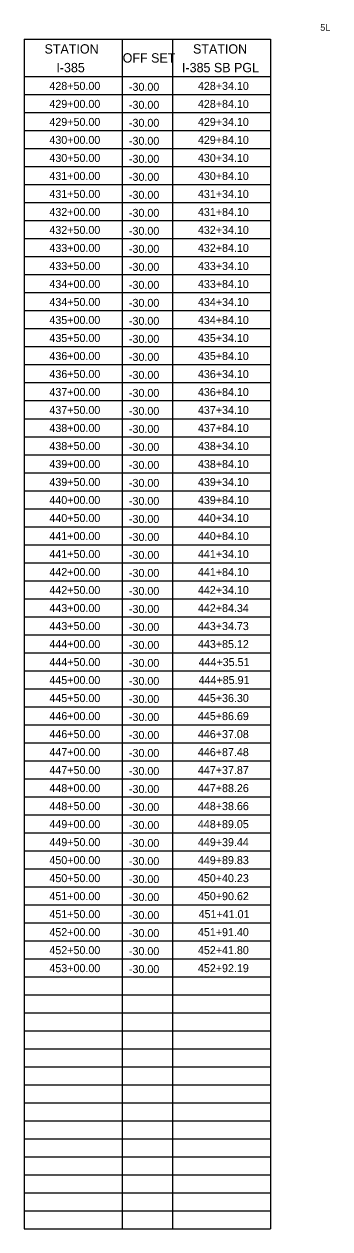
# Model space of a CAD drawing. Extents: x 1602163 to 1612907, y 1087635 to 1096265.
# Drawn here: x 1610961 to 1611190, y 1095298 to 1096201 of the extents above; entities that cross this region are included whole.
import ezdxf

# ---------------------------------------------------------------- set-up
doc = ezdxf.new("R2010")
doc.units = 0
for name, color, linetype in [('RD_SHT_Bndy', 7, 'Continuous'), ('RD_SHT_Misc1', 7, 'Continuous'), ('RD_SHT_TX', 7, 'Continuous')]:
    doc.layers.add(name, color=color, linetype=linetype)

msp = doc.modelspace()

# ---------------------------------------------------------------- linework, layer by layer
at = {"layer": 'RD_SHT_Misc1'}
for p, q in [((1610961.15, 1096189.84), (1610961.15, 1095297.84)), ((1610961.15, 1096189.84), (1611145.98, 1096189.84)), ((1611034.62, 1096189.84), (1611034.62, 1095297.84)), ((1611072.51, 1096189.84), (1611072.51, 1095297.84)), ((1611145.98, 1096189.84), (1611145.98, 1095297.84)), ((1610961.15, 1096161.84), (1611145.98, 1096161.84)), ((1610961.15, 1096148.34), (1611145.98, 1096148.34)), ((1610961.15, 1096134.84), (1611145.98, 1096134.84)), ((1610961.15, 1096121.34), (1611145.98, 1096121.34)), ((1610961.15, 1096107.84), (1611145.98, 1096107.84)), ((1610961.15, 1096094.34), (1611145.98, 1096094.34)), ((1610961.15, 1096080.84), (1611145.98, 1096080.84)), ((1610961.15, 1096067.34), (1611145.98, 1096067.34)), ((1610961.15, 1096053.84), (1611145.98, 1096053.84)), ((1610961.15, 1096040.34), (1611145.98, 1096040.34)), ((1610961.15, 1096026.84), (1611145.98, 1096026.84)), ((1610961.15, 1096013.34), (1611145.98, 1096013.34)), ((1610961.15, 1095999.84), (1611145.98, 1095999.84)), ((1610961.15, 1095986.34), (1611145.98, 1095986.34)), ((1610961.15, 1095972.84), (1611145.98, 1095972.84)), ((1610961.15, 1095959.34), (1611145.98, 1095959.34)), ((1610961.15, 1095945.84), (1611145.98, 1095945.84)), ((1610961.15, 1095932.34), (1611145.98, 1095932.34)), ((1610961.15, 1095918.84), (1611145.98, 1095918.84)), ((1610961.15, 1095905.34), (1611145.98, 1095905.34)), ((1610961.15, 1095891.84), (1611145.98, 1095891.84)), ((1610961.15, 1095878.34), (1611145.98, 1095878.34)), ((1610961.15, 1095864.84), (1611145.98, 1095864.84)), ((1610961.15, 1095851.34), (1611145.98, 1095851.34)), ((1610961.15, 1095837.84), (1611145.98, 1095837.84)), ((1610961.15, 1095824.34), (1611145.98, 1095824.34)), ((1610961.15, 1095810.84), (1611145.98, 1095810.84)), ((1610961.15, 1095797.34), (1611145.98, 1095797.34)), ((1610961.15, 1095783.84), (1611145.98, 1095783.84)), ((1610961.15, 1095770.34), (1611145.98, 1095770.34)), ((1610961.15, 1095756.84), (1611145.98, 1095756.84)), ((1610961.15, 1095743.34), (1611145.98, 1095743.34)), ((1610961.15, 1095729.84), (1611145.98, 1095729.84)), ((1610961.15, 1095716.34), (1611145.98, 1095716.34)), ((1610961.15, 1095702.84), (1611145.98, 1095702.84)), ((1610961.15, 1095689.34), (1611145.98, 1095689.34)), ((1610961.15, 1095675.84), (1611145.98, 1095675.84)), ((1610961.15, 1095662.34), (1611145.98, 1095662.34)), ((1610961.15, 1095648.84), (1611145.98, 1095648.84)), ((1610961.15, 1095635.34), (1611145.98, 1095635.34)), ((1610961.15, 1095621.84), (1611145.98, 1095621.84)), ((1610961.15, 1095608.34), (1611145.98, 1095608.34)), ((1610961.15, 1095594.84), (1611145.98, 1095594.84)), ((1610961.15, 1095581.34), (1611145.98, 1095581.34)), ((1610961.15, 1095567.84), (1611145.98, 1095567.84)), ((1610961.15, 1095554.34), (1611145.98, 1095554.34)), ((1610961.15, 1095540.84), (1611145.98, 1095540.84)), ((1610961.15, 1095527.34), (1611145.98, 1095527.34)), ((1610961.15, 1095513.84), (1611145.98, 1095513.84)), ((1610961.15, 1095500.34), (1611145.98, 1095500.34)), ((1610961.15, 1095486.84), (1611145.98, 1095486.84)), ((1610961.15, 1095473.34), (1611145.98, 1095473.34)), ((1610961.15, 1095459.84), (1611145.98, 1095459.84)), ((1610961.15, 1095446.34), (1611145.98, 1095446.34)), ((1610961.15, 1095432.84), (1611145.98, 1095432.84)), ((1610961.15, 1095419.34), (1611145.98, 1095419.34)), ((1610961.15, 1095405.84), (1611145.98, 1095405.84)), ((1610961.15, 1095392.34), (1611145.98, 1095392.34)), ((1610961.15, 1095378.84), (1611145.98, 1095378.84)), ((1610961.15, 1095365.34), (1611145.98, 1095365.34)), ((1610961.15, 1095351.84), (1611145.98, 1095351.84)), ((1610961.15, 1095338.34), (1611145.98, 1095338.34)), ((1610961.15, 1095324.84), (1611145.98, 1095324.84)), ((1610961.15, 1095311.34), (1611145.98, 1095311.34)), ((1610961.15, 1095297.84), (1611145.98, 1095297.84))]:
    msp.add_line(p, q, dxfattribs=at)

# ---------------------------------------------------------------- texts
at = {"layer": 'RD_SHT_Bndy'}
msp.add_text('5L', height=5, dxfattribs=at).set_placement((1611183.24, 1096196.19))
at = {"layer": 'RD_SHT_TX'}
for s, height, p in [('STATION', 7, (1610976.47, 1096179.07)), ('OFF SET', 7, (1611035.07, 1096172.34)), ('STATION', 7, (1611087.83, 1096179.07)), ('I-385', 7, (1610985.34, 1096165.07)), ('I-385 SB PGL', 7, (1611079.55, 1096165.07)), ('428+50.00', 6, (1610980.14, 1096151.84)), ('-30.00', 6, (1611039.78, 1096151.15)), ('428+34.10', 6, (1611091.5, 1096151.84)), ('429+00.00', 6, (1610980.14, 1096138.34)), ('-30.00', 6, (1611039.78, 1096137.65)), ('428+84.10', 6, (1611091.5, 1096138.34)), ('429+50.00', 6, (1610980.14, 1096124.84)), ('-30.00', 6, (1611039.78, 1096124.15)), ('429+34.10', 6, (1611091.5, 1096124.84)), ('430+00.00', 6, (1610980.14, 1096111.34)), ('-30.00', 6, (1611039.78, 1096110.65)), ('429+84.10', 6, (1611091.5, 1096111.34)), ('430+50.00', 6, (1610980.14, 1096097.84)), ('-30.00', 6, (1611039.78, 1096097.15)), ('430+34.10', 6, (1611091.5, 1096097.84)), ('431+00.00', 6, (1610980.14, 1096084.34)), ('-30.00', 6, (1611039.78, 1096083.65)), ('430+84.10', 6, (1611091.5, 1096084.34)), ('431+50.00', 6, (1610980.14, 1096070.84)), ('-30.00', 6, (1611039.78, 1096070.15)), ('431+34.10', 6, (1611091.5, 1096070.84)), ('432+00.00', 6, (1610980.14, 1096057.34)), ('-30.00', 6, (1611039.78, 1096056.65)), ('431+84.10', 6, (1611091.5, 1096057.34)), ('432+50.00', 6, (1610980.14, 1096043.84)), ('-30.00', 6, (1611039.78, 1096043.15)), ('432+34.10', 6, (1611091.5, 1096043.84)), ('433+00.00', 6, (1610980.14, 1096030.34)), ('-30.00', 6, (1611039.78, 1096029.65)), ('432+84.10', 6, (1611091.5, 1096030.34)), ('433+50.00', 6, (1610980.14, 1096016.84)), ('-30.00', 6, (1611039.78, 1096016.15)), ('433+34.10', 6, (1611091.5, 1096016.84)), ('434+00.00', 6, (1610980.14, 1096003.34)), ('-30.00', 6, (1611039.78, 1096002.65)), ('433+84.10', 6, (1611091.5, 1096003.34)), ('434+50.00', 6, (1610980.14, 1095989.84)), ('-30.00', 6, (1611039.78, 1095989.15)), ('434+34.10', 6, (1611091.5, 1095989.84)), ('435+00.00', 6, (1610980.14, 1095976.34)), ('-30.00', 6, (1611039.78, 1095975.65)), ('434+84.10', 6, (1611091.5, 1095976.34)), ('435+50.00', 6, (1610980.14, 1095962.84)), ('-30.00', 6, (1611039.78, 1095962.15)), ('435+34.10', 6, (1611091.5, 1095962.84)), ('436+00.00', 6, (1610980.14, 1095949.34)), ('-30.00', 6, (1611039.78, 1095948.65)), ('435+84.10', 6, (1611091.5, 1095949.34)), ('436+50.00', 6, (1610980.14, 1095935.84)), ('-30.00', 6, (1611039.78, 1095935.15)), ('436+34.10', 6, (1611091.5, 1095935.84)), ('437+00.00', 6, (1610980.14, 1095922.34)), ('-30.00', 6, (1611039.78, 1095921.65)), ('436+84.10', 6, (1611091.5, 1095922.34)), ('437+50.00', 6, (1610980.14, 1095908.84)), ('-30.00', 6, (1611039.78, 1095908.15)), ('437+34.10', 6, (1611091.5, 1095908.84)), ('438+00.00', 6, (1610980.14, 1095895.34)), ('-30.00', 6, (1611039.78, 1095894.65)), ('437+84.10', 6, (1611091.5, 1095895.34)), ('438+50.00', 6, (1610980.14, 1095881.84)), ('-30.00', 6, (1611039.78, 1095881.15)), ('438+34.10', 6, (1611091.5, 1095881.84)), ('439+00.00', 6, (1610980.14, 1095868.34)), ('-30.00', 6, (1611039.78, 1095867.65)), ('438+84.10', 6, (1611091.5, 1095868.34)), ('439+50.00', 6, (1610980.14, 1095854.84)), ('-30.00', 6, (1611039.78, 1095854.15)), ('439+34.10', 6, (1611091.5, 1095854.84)), ('440+00.00', 6, (1610980.14, 1095841.34)), ('-30.00', 6, (1611039.78, 1095840.65)), ('439+84.10', 6, (1611091.5, 1095841.34)), ('440+50.00', 6, (1610980.14, 1095827.84)), ('-30.00', 6, (1611039.78, 1095827.15)), ('440+34.10', 6, (1611091.5, 1095827.84)), ('441+00.00', 6, (1610980.14, 1095814.34)), ('-30.00', 6, (1611039.78, 1095813.65)), ('440+84.10', 6, (1611091.5, 1095814.34)), ('441+50.00', 6, (1610980.14, 1095800.84)), ('-30.00', 6, (1611039.78, 1095800.15)), ('441+34.10', 6, (1611091.5, 1095800.84)), ('442+00.00', 6, (1610980.14, 1095787.34)), ('-30.00', 6, (1611039.78, 1095786.65)), ('441+84.10', 6, (1611091.5, 1095787.34)), ('442+50.00', 6, (1610980.14, 1095773.84)), ('-30.00', 6, (1611039.78, 1095773.15)), ('442+34.10', 6, (1611091.5, 1095773.84)), ('443+00.00', 6, (1610980.14, 1095760.34)), ('-30.00', 6, (1611039.78, 1095759.65)), ('442+84.34', 6, (1611091.5, 1095760.34)), ('443+50.00', 6, (1610980.14, 1095746.84)), ('-30.00', 6, (1611039.78, 1095746.15)), ('443+34.73', 6, (1611091.49, 1095746.84)), ('444+00.00', 6, (1610980.14, 1095733.34)), ('-30.00', 6, (1611039.78, 1095732.65)), ('443+85.12', 6, (1611091.52, 1095733.34)), ('444+50.00', 6, (1610980.14, 1095719.84)), ('-30.00', 6, (1611039.78, 1095719.15)), ('444+35.51', 6, (1611092.01, 1095719.84)), ('445+00.00', 6, (1610980.14, 1095706.34)), ('-30.00', 6, (1611039.78, 1095705.65)), ('444+85.91', 6, (1611092.01, 1095706.34)), ('445+50.00', 6, (1610980.14, 1095692.84)), ('-30.00', 6, (1611039.78, 1095692.15)), ('445+36.30', 6, (1611091.5, 1095692.84)), ('446+00.00', 6, (1610980.14, 1095679.34)), ('-30.00', 6, (1611039.78, 1095678.65)), ('445+86.69', 6, (1611091.49, 1095679.34)), ('446+50.00', 6, (1610980.14, 1095665.84)), ('-30.00', 6, (1611039.78, 1095665.15)), ('446+37.08', 6, (1611091.49, 1095665.84)), ('447+00.00', 6, (1610980.14, 1095652.34)), ('-30.00', 6, (1611039.78, 1095651.65)), ('446+87.48', 6, (1611091.49, 1095652.34)), ('447+50.00', 6, (1610980.14, 1095638.84)), ('-30.00', 6, (1611039.78, 1095638.15)), ('447+37.87', 6, (1611091.49, 1095638.84)), ('448+00.00', 6, (1610980.14, 1095625.34)), ('-30.00', 6, (1611039.78, 1095624.65)), ('447+88.26', 6, (1611091.49, 1095625.34)), ('448+50.00', 6, (1610980.14, 1095611.84)), ('-30.00', 6, (1611039.78, 1095611.15)), ('448+38.66', 6, (1611091.49, 1095611.84)), ('449+00.00', 6, (1610980.14, 1095598.34)), ('-30.00', 6, (1611039.78, 1095597.65)), ('448+89.05', 6, (1611091.47, 1095598.34)), ('449+50.00', 6, (1610980.14, 1095584.84)), ('-30.00', 6, (1611039.78, 1095584.15)), ('449+39.44', 6, (1611091.5, 1095584.84)), ('450+00.00', 6, (1610980.14, 1095571.34)), ('-30.00', 6, (1611039.78, 1095570.65)), ('449+89.83', 6, (1611091.49, 1095571.34)), ('450+50.00', 6, (1610980.14, 1095557.84)), ('-30.00', 6, (1611039.78, 1095557.15)), ('450+40.23', 6, (1611091.49, 1095557.84)), ('451+00.00', 6, (1610980.14, 1095544.34)), ('-30.00', 6, (1611039.78, 1095543.65)), ('450+90.62', 6, (1611091.52, 1095544.34)), ('451+50.00', 6, (1610980.14, 1095530.84)), ('-30.00', 6, (1611039.78, 1095530.15)), ('451+41.01', 6, (1611092.01, 1095530.84)), ('452+00.00', 6, (1610980.14, 1095517.34)), ('-30.00', 6, (1611039.78, 1095516.65)), ('451+91.40', 6, (1611091.5, 1095517.34)), ('452+50.00', 6, (1610980.14, 1095503.84)), ('-30.00', 6, (1611039.78, 1095503.15)), ('452+41.80', 6, (1611091.5, 1095503.84)), ('453+00.00', 6, (1610980.14, 1095490.34)), ('-30.00', 6, (1611039.78, 1095489.65)), ('452+92.19', 6, (1611091.49, 1095490.34))]:
    msp.add_text(s, height=height, dxfattribs=at).set_placement(p)

doc.saveas('drawing.dxf')
